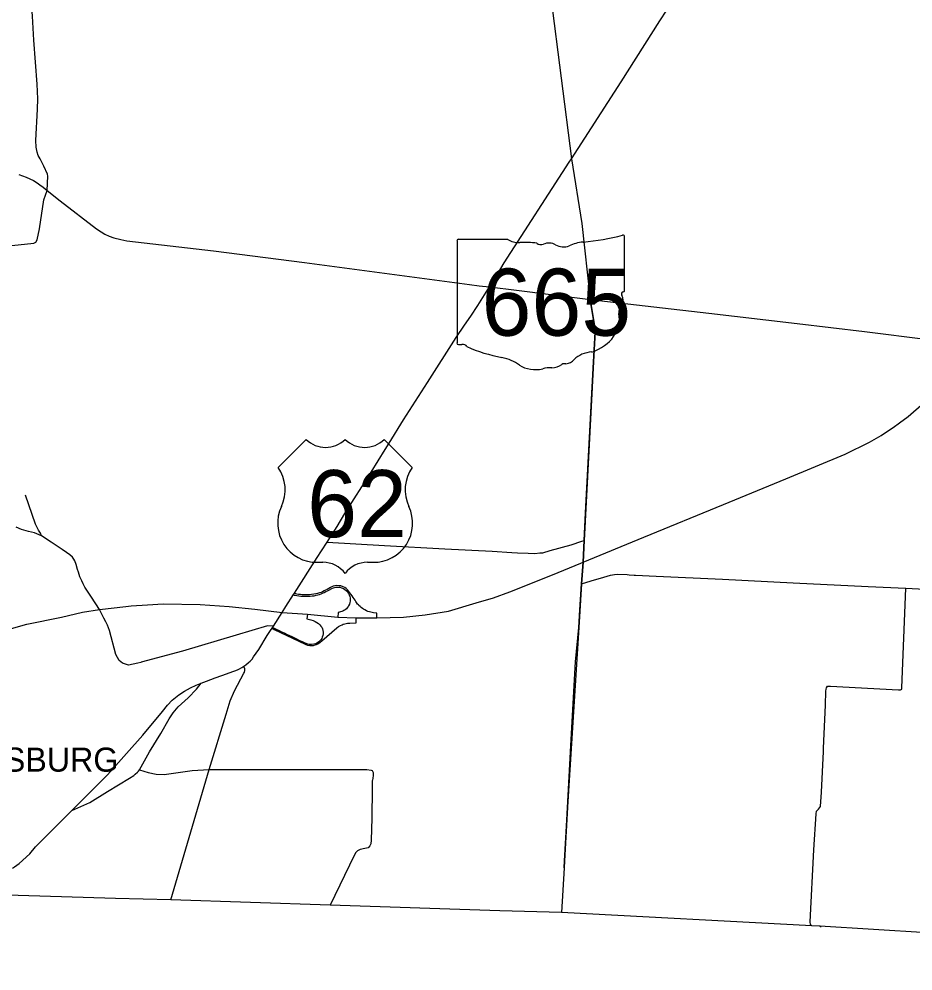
# Model space of a CAD drawing. Extents: x 1755200 to 1902939, y 644115 to 788070.
# Drawn here: x 1782951 to 1801507, y 657827 to 677595 of the extents above; entities that cross this region are included whole.
import ezdxf

# ---------------------------------------------------------------- set-up
doc = ezdxf.new("R2010")
doc.units = 0
for name, color, linetype in [('GM_X_Corporation_Text', 7, 'Continuous'), ('GM_X_County', 7, 'Continuous'), ('GM_X_County_Road', 7, 'Continuous'), ('GM_X_Interchange_Ramps', 7, 'Continuous'), ('GM_X_Interstate_Route', 7, 'Continuous'), ('GM_X_State_Route', 7, 'Continuous'), ('GM_X_State_Shield', 7, 'Continuous'), ('GM_X_Township', 7, 'Continuous'), ('GM_X_Township_Road', 7, 'Continuous'), ('GM_X_US_Route', 7, 'Continuous'), ('GM_X_US_Shield', 7, 'Continuous')]:
    doc.layers.add(name, color=color, linetype=linetype)

msp = doc.modelspace()

# ---------------------------------------------------------------- linework, layer by layer
at = {"layer": 'GM_X_County'}
msp.add_lwpolyline([(1819565, 657827), (1815551, 657995), (1815251, 658006), (1814713, 658027), (1811039, 658133), (1807036, 658278), (1802918, 658549), (1799575, 658756), (1799409, 658764), (1794213, 659039), (1792928, 659077), (1789408, 659196), (1786100, 659304), (1784956, 659328), (1781576, 659434)], dxfattribs=at)
at = {"layer": 'GM_X_County_Road'}
for points in [[(1782799, 672895), (1783258, 672938), (1783298, 672959), (1783324, 673007), (1783374, 673235), (1783468, 673837), (1783535, 674036), (1783550, 674333), (1783542, 674374), (1783468, 674540), (1783387, 674689), (1783347, 674762), (1783328, 674832), (1783304, 674932), (1783299, 675075), (1783336, 675721), (1783338, 675938), (1783324, 676240), (1783261, 677156), (1783230, 677651), (1783198, 678124), (1783187, 678273), (1783142, 678403), (1782923, 678824)], [(1784167, 666166), (1784139, 666268), (1784110, 666342), (1784086, 666380), (1784060, 666419), (1784007, 666466), (1783937, 666518), (1783844, 666582), (1783619, 666732), (1783419, 666860), (1783270, 666922), (1783149, 666951), (1783002, 666997), (1782890, 667046)], [(1789344, 666734), (1790537, 666661), (1791789, 666590), (1792769, 666542), (1793180, 666519), (1793295, 666513)], [(1793295, 666513), (1793517, 666503), (1793658, 666499), (1793762, 666507), (1793824, 666510), (1793979, 666556), (1794410, 666679), (1794631, 666749)], [(1794631, 666749), (1794681, 666765)], [(1785488, 664237), (1785482, 664235), (1785415, 664217), (1785225, 664179), (1785099, 664218), (1785031, 664276), (1784960, 664401), (1784830, 664895), (1784787, 665008), (1784751, 665076), (1784708, 665153), (1784623, 665333), (1784452, 665588), (1784319, 665794), (1784282, 665863), (1784251, 665928), (1784214, 666014), (1784184, 666108), (1784167, 666166)], [(1794628, 665869), (1794828, 665926), (1795089, 666006), (1795229, 666043), (1795313, 666060), (1795373, 666064), (1795571, 666063), (1795618, 666051), (1795717, 666046), (1795747, 666045)], [(1795747, 666045), (1796176, 666025), (1797552, 665961), (1799023, 665886), (1800577, 665809), (1801360, 665776), (1801750, 665758), (1801954, 665741), (1802014, 665745), (1802050, 665761), (1802068, 665780), (1802080, 665822), (1802087, 665905)], [(1788230, 664988), (1788111, 664995), (1787461, 664802), (1786344, 664466), (1785488, 664237)], [(1786100, 659304), (1786899, 662007), (1787247, 663159), (1787335, 663439), (1787423, 663644), (1787619, 664011), (1787633, 664034), (1787638, 664068), (1787636, 664100), (1787627, 664132), (1787616, 664155)]]:
    msp.add_lwpolyline(points, dxfattribs=at)
at = {"layer": 'GM_X_Interchange_Ramps'}
for points in [[(1788648, 665645), (1788671, 665631), (1788715, 665621), (1788758, 665616), (1788803, 665612), (1788844, 665609), (1788882, 665608), (1788922, 665607), (1788954, 665607), (1788993, 665609), (1789037, 665614), (1789079, 665620), (1789119, 665628), (1789156, 665637), (1789189, 665647), (1789224, 665659), (1789251, 665669), (1789283, 665685), (1789319, 665704), (1789351, 665720), (1789383, 665737), (1789442, 665769), (1789479, 665786), (1789526, 665797), (1789564, 665799), (1789607, 665796), (1789646, 665786), (1789687, 665769), (1789717, 665749), (1789749, 665723), (1789770, 665698), (1789790, 665668), (1789806, 665637), (1789817, 665605), (1789823, 665573), (1789825, 665540), (1789823, 665505), (1789818, 665476), (1789807, 665441), (1789792, 665410), (1789782, 665393), (1789762, 665367), (1789745, 665348), (1789722, 665329), (1789695, 665311), (1789673, 665299), (1789648, 665290), (1789574, 665271), (1789566, 665173)], [(1790378, 665161), (1790379, 665260), (1790311, 665265), (1790282, 665269), (1790252, 665275), (1790224, 665283), (1790191, 665294), (1790163, 665305), (1790126, 665324), (1790100, 665339), (1790077, 665355), (1790054, 665372), (1790029, 665394), (1790007, 665415), (1789996, 665428), (1789979, 665447), (1789957, 665476), (1789945, 665496), (1789925, 665526), (1789905, 665554), (1789885, 665584), (1789864, 665614), (1789839, 665651), (1789818, 665681), (1789799, 665709), (1789770, 665743), (1789743, 665767), (1789715, 665787), (1789676, 665806), (1789633, 665821), (1789593, 665827), (1789548, 665829), (1789508, 665824), (1789471, 665814), (1789442, 665802), (1789418, 665790), (1789380, 665769), (1789346, 665751), (1789313, 665734), (1789285, 665719), (1789253, 665703), (1789219, 665689), (1789185, 665677), (1789144, 665665), (1789113, 665658), (1789070, 665649), (1789024, 665642), (1788981, 665638), (1788940, 665637), (1788902, 665637), (1788866, 665638), (1788831, 665640), (1788795, 665643), (1788754, 665646), (1788716, 665651), (1788690, 665656), (1788666, 665672)], [(1788936, 665236), (1788928, 665136), (1789009, 665119), (1789058, 665104), (1789096, 665087), (1789133, 665066), (1789166, 665041), (1789197, 665012), (1789217, 664990), (1789234, 664966), (1789249, 664931), (1789258, 664897), (1789263, 664860), (1789262, 664827), (1789257, 664795), (1789245, 664759), (1789233, 664734), (1789216, 664706), (1789197, 664683), (1789173, 664660), (1789144, 664640), (1789109, 664622), (1789070, 664611), (1789022, 664605), (1788971, 664608), (1788926, 664619), (1788876, 664641), (1788838, 664659), (1788782, 664685), (1788734, 664708), (1788674, 664737), (1788617, 664764), (1788570, 664786), (1788522, 664809), (1788461, 664838), (1788409, 664863), (1788356, 664888), (1788308, 664911), (1788255, 664936), (1788213, 664962)], [(1788202, 664945), (1788246, 664917), (1788890, 664611), (1788940, 664593), (1788986, 664586), (1789026, 664585), (1789063, 664588), (1789100, 664597), (1789125, 664606), (1789168, 664630), (1789233, 664685), (1789547, 664951), (1789583, 664978), (1789623, 665001), (1789655, 665017), (1789680, 665026), (1789716, 665038), (1789771, 665048), (1789819, 665052), (1789947, 665059), (1789948, 665161)]]:
    msp.add_lwpolyline(points, dxfattribs=at)
at = {"layer": 'GM_X_Interstate_Route'}
for points in [[(1801226, 669208), (1801405, 669341), (1801729, 669625), (1801864, 669759), (1802106, 670017), (1802426, 670424), (1802697, 670834)], [(1800959, 669021), (1801098, 669113), (1801226, 669208)], [(1794609, 666298), (1794658, 666318), (1795918, 666832), (1797576, 667510), (1798866, 668046), (1800101, 668557), (1800602, 668805), (1800850, 668949), (1800959, 669021)], [(1788411, 665272), (1788936, 665236), (1789566, 665173), (1789948, 665161), (1790378, 665161), (1790931, 665174), (1791380, 665222), (1791866, 665300), (1792438, 665469), (1792800, 665575), (1793140, 665698), (1794026, 666055), (1794609, 666298)], [(1782399, 664828), (1783114, 665027), (1783830, 665175), (1784266, 665280), (1784623, 665333), (1785169, 665398), (1785278, 665407), (1785620, 665431), (1785943, 665448), (1786709, 665435), (1787312, 665395), (1787847, 665340), (1788411, 665272)]]:
    msp.add_lwpolyline(points, dxfattribs=at)
at = {"layer": 'GM_X_State_Route'}
for points in [[(1782945, 674365), (1783098, 674311), (1783174, 674276), (1783251, 674240), (1783326, 674193), (1783381, 674155), (1783451, 674103), (1783535, 674036), (1783804, 673822), (1784562, 673240), (1784654, 673177), (1784734, 673128), (1784820, 673089), (1784919, 673053), (1785066, 673017), (1785185, 672991), (1785368, 672966), (1786989, 672782), (1788878, 672539), (1792298, 672084), (1792500, 672057), (1792717, 672032)], [(1792717, 672032), (1793275, 671961), (1794757, 671777)], [(1794757, 671777), (1794806, 671771), (1797266, 671486), (1797804, 671424), (1799105, 671270), (1800498, 671103), (1801820, 670938), (1801979, 670920)]]:
    msp.add_lwpolyline(points, dxfattribs=at)
at = {"layer": 'GM_X_State_Shield'}
for p, q in [((1792042, 672983), (1792042, 670870)), ((1793095, 673019), (1792076, 673019)), ((1795522, 671966), (1795522, 673072)), ((1795522, 671967), (1795522, 671966))]:
    msp.add_line(p, q, dxfattribs=at)
for centre, major_axis, start_param, end_param in [((1794282, 675901), (3691, 0), 4.814394, 5.042369), ((1795483, 673076), (38.7, 0), 6.141152, 7.989035), ((1792081, 672988), (40.3, 0), 1.712693, 3.28349), ((1793338, 673265), (391, 0), 4.042523, 4.731795), ((1793467, 671833), (1404, 0), 1.404758, 1.657858), ((1793786, 672999), (113, 0), 3.836095, 5.185415), ((1793952, 672754), (235, 0), 0.950623, 2.079405), ((1794255, 673089), (282, 0), 4.081561, 5.145723), ((1794753, 672374), (743, 0), 1.699011, 2.107814), ((1795513, 671885), (60, 0), 1.883978, 3.671073), ((1795481, 671962), (41.5, 0), 5.05454, 6.418171), ((1795132, 671745), (360, 0), 5.934695, 6.695948), ((1795661, 671504), (262, 0), 2.387724, 3.262537), ((1794489, 671363), (923, 0), 5.101752, 6.440018), ((1792082, 670865), (40.7, 0), 3.00124, 4.508301), ((1792088, 671081), (310, 0), 4.665946, 4.897461), ((1792151, 670748), (112, 0), 0.519207, 1.627899), ((1793565, 672647), (2665, 0), 4.195997, 4.488961), ((1792770, 669920), (834, 0), 0.823519, 1.323587), ((1794878, 670277), (506, 0), 1.647645, 2.488434), ((1793672, 670737), (529, 0), 4.026481, 4.996735), ((1793978, 670007), (435, 0), 1.495662, 1.94098), ((1794016, 670579), (282, 0), 4.691044, 5.507374), ((1794271, 670374), (79.4, 0), 1.147584, 2.315152), ((1794238, 670665), (298, 0), 4.937069, 5.64225)]:
    msp.add_ellipse(centre, major_axis=major_axis, ratio=0.8, start_param=start_param, end_param=end_param, dxfattribs=at)
at = {"layer": 'GM_X_Township'}
msp.add_lwpolyline([(1793990, 678050), (1794416, 674693), (1794635, 673347), (1794806, 671771), (1794893, 671228), (1794908, 671097), (1794874, 670478), (1794681, 666765), (1794658, 666318), (1794628, 665869), (1794571, 664962), (1794341, 661348), (1794272, 660115), (1794265, 659967), (1794213, 659039)], dxfattribs=at)
at = {"layer": 'GM_X_Township_Road'}
for points in [[(1794711, 667339), (1794874, 670478), (1794908, 671097), (1794893, 671228), (1794806, 671771)], [(1783419, 666860), (1783397, 666917), (1783353, 666983), (1783295, 667108), (1783084, 667706)], [(1794628, 665869), (1794658, 666318), (1794681, 666765), (1794711, 667339)], [(1794594, 665324), (1794628, 665869)], [(1799648, 662419), (1799650, 662451), (1799688, 663348), (1799698, 663637), (1799703, 663679), (1799715, 663708), (1799736, 663740), (1799796, 663743), (1801206, 663665), (1801248, 663664), (1801274, 663678), (1801279, 663708), (1801360, 665776)], [(1794312, 660830), (1794341, 661348), (1794413, 662634), (1794505, 664244), (1794571, 664962), (1794594, 665324)], [(1784050, 661158), (1784421, 661328), (1784785, 661553), (1785245, 661832), (1785332, 661887), (1785362, 661915), (1785407, 661955), (1785429, 661979), (1785449, 662005), (1785660, 662374), (1785891, 662758), (1786065, 663060), (1786148, 663185), (1786257, 663311), (1786461, 663499), (1786634, 663678), (1786734, 663801)], [(1799409, 658764), (1799379, 658791), (1799373, 658847), (1799448, 660342), (1799494, 661089), (1799505, 661143), (1799544, 661188), (1799589, 661239), (1799607, 661542), (1799647, 662387), (1799648, 662419)], [(1785449, 662005), (1785631, 661949), (1785794, 661914), (1785961, 661904), (1786544, 661990), (1786899, 662007), (1790170, 662010), (1790258, 661999), (1790282, 661987), (1790304, 661949), (1790304, 661888), (1790293, 661830), (1790285, 661792), (1790284, 661772)], [(1790284, 661772), (1790284, 661736), (1790282, 661618), (1790271, 661003), (1790262, 660542), (1790255, 660466), (1790233, 660426), (1790200, 660384), (1790128, 660371), (1790032, 660347), (1789976, 660322), (1789939, 660284), (1789905, 660222), (1789408, 659196)], [(1794265, 659967), (1794272, 660115), (1794312, 660830)], [(1799600, 658737), (1799575, 658756), (1799409, 658764)]]:
    msp.add_lwpolyline(points, dxfattribs=at)
at = {"layer": 'GM_X_US_Route'}
for points in [[(1794369, 674621), (1794416, 674693), (1795452, 676291), (1796252, 677554), (1796540, 678009)], [(1792717, 672032), (1792863, 672264), (1793021, 672532), (1794369, 674621)], [(1790554, 668655), (1790636, 668785), (1790931, 669274), (1791427, 670046), (1792022, 670984), (1792196, 671234), (1792328, 671423), (1792474, 671646), (1792717, 672032)], [(1788666, 665672), (1789138, 666416), (1789230, 666553), (1789344, 666734), (1789553, 667059), (1789715, 667323), (1790257, 668184), (1790554, 668655)], [(1788490, 665396), (1788648, 665645), (1788666, 665672)], [(1788171, 664896), (1788202, 664945), (1788213, 664962), (1788230, 664988), (1788411, 665272), (1788490, 665396)], [(1787043, 663919), (1787255, 663998), (1787392, 664047), (1787427, 664059), (1787486, 664082), (1787528, 664103), (1787574, 664128), (1787616, 664155), (1787658, 664184), (1787715, 664230), (1787748, 664259), (1787789, 664303), (1787821, 664347), (1787928, 664501), (1788104, 664792), (1788171, 664896)], [(1782818, 659962), (1782858, 659989), (1782950, 660058), (1783174, 660262), (1783295, 660401), (1784050, 661158), (1784789, 661898), (1785521, 662721), (1785931, 663218), (1786031, 663343), (1786129, 663449), (1786199, 663506), (1786267, 663559), (1786382, 663639), (1786511, 663709), (1786630, 663762), (1786734, 663801), (1786844, 663844), (1787022, 663911), (1787043, 663919)]]:
    msp.add_lwpolyline(points, dxfattribs=at)
at = {"layer": 'GM_X_US_Shield'}
for p, q in [((1788908, 668865), (1788328, 668285)), ((1791112, 668285), (1790532, 668865)), ((1789140, 666313), (1789256, 666313)), ((1790184, 666313), (1790300, 666313))]:
    msp.add_line(p, q, dxfattribs=at)
for centre, radius, start, end in [((1789314, 669280), 580, 225.573, 314.427), ((1790126, 669280), 580, 225.573, 314.427), ((1787663, 667819), 812, 334.5471, 35.0009), ((1791778, 667819), 812, 144.9991, 205.4529), ((1789131, 667125), 812, 154.8319, 270.6383), ((1790309, 667125), 812, 269.3617, 25.1681), ((1789256, 665733), 580, 36.8699, 90), ((1790184, 665733), 580, 90, 143.1301)]:
    msp.add_arc(centre, radius, start, end, dxfattribs=at)

# ---------------------------------------------------------------- texts
at = {"layer": 'GM_X_Corporation_Text'}
msp.add_text('HARRISBURG', height=500, rotation=0, dxfattribs=at).set_placement((1780555, 661965))
at = {"layer": 'GM_X_State_Shield'}
msp.add_text('665', height=1392.2, dxfattribs=at).set_placement((1792552, 671019))
at = {"layer": 'GM_X_US_Shield'}
msp.add_text('62', height=1392.2, dxfattribs=at).set_placement((1788932, 666835))

doc.saveas('drawing.dxf')
